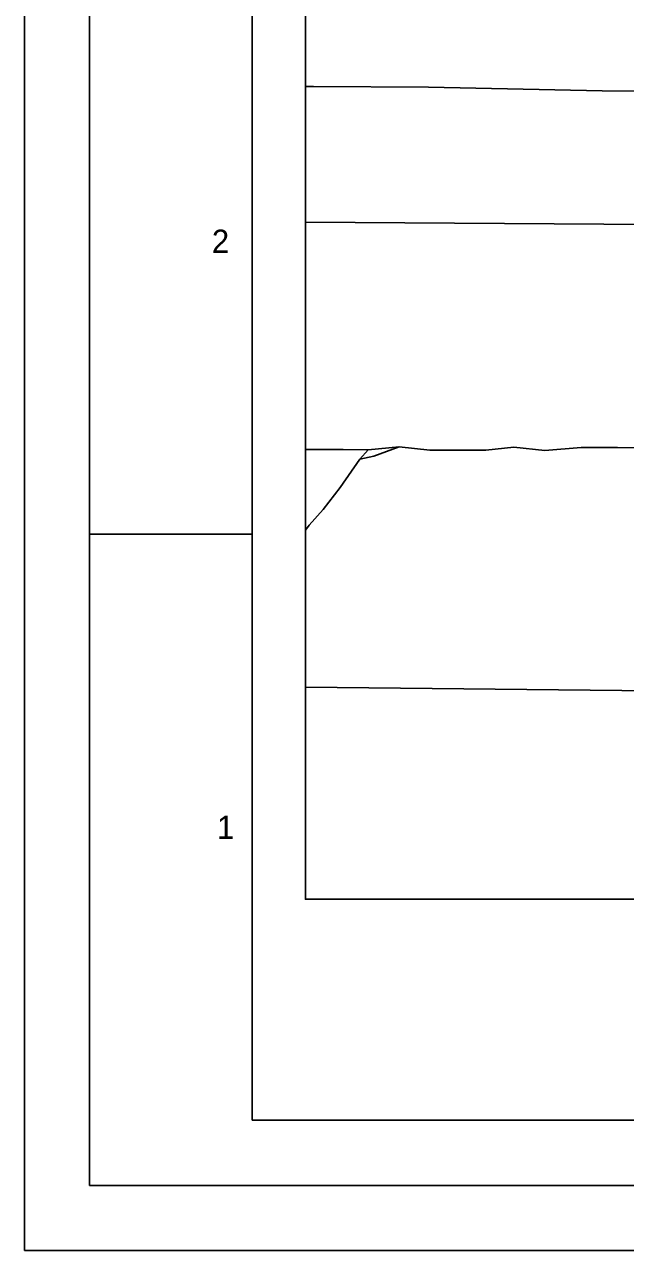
# Model space of a CAD drawing. Extents: x 492225 to 553725, y 1303773 to 1347273.
# Drawn here: x 492225 to 499152, y 1303773 to 1317894 of the extents above; entities that cross this region are included whole.
import ezdxf

# ---------------------------------------------------------------- set-up
doc = ezdxf.new("R2010")
doc.units = 0
for name, color, linetype in [('G-ANNO-TTLB', 7, 'Continuous'), ('Level 1', 7, 'Continuous'), ('Level 13', 7, 'Continuous'), ('Level 22', 7, 'Continuous'), ('Level 52', 7, 'Continuous')]:
    doc.layers.add(name, color=color, linetype=linetype)

msp = doc.modelspace()

# ---------------------------------------------------------------- linework, layer by layer
at = {"layer": 'G-ANNO-TTLB'}
for p, q in [((492975.069, 1346522.564), (492975.069, 1304522.564)), ((494850.069, 1305272.564), (494850.069, 1345772.564)), ((494850.069, 1312022.564), (492975.069, 1312022.564)), ((552225.069, 1305272.564), (494850.069, 1305272.564)), ((492975.069, 1304522.564), (552975.069, 1304522.564))]:
    msp.add_line(p, q, dxfattribs=at)
for points in [[(492225.069, 1303772.564), (553725.069, 1303772.564), (553725.069, 1347272.564), (492225.069, 1347272.564)], [(492225.069, 1303772.564), (553725.069, 1303772.564), (553725.069, 1347272.564), (492225.069, 1347272.564)], [(492225.069, 1347272.564), (553725.069, 1347272.564), (553725.069, 1303772.564), (492225.069, 1303772.564)]]:
    msp.add_lwpolyline(points, close=True, dxfattribs=at)
msp.add_lwpolyline([(492225.069, 1304147.564), (492225.069, 1303772.564), (492600.069, 1303772.564)], dxfattribs=at)
at = {"layer": 'Level 1'}
for p, q in [((499586.966, 1315590.825), (495463.793, 1315618.6072)), ((499556.27, 1310217.447), (495463.793, 1310260.1265))]:
    msp.add_line(p, q, dxfattribs=at)
at = {"layer": 'Level 13'}
for p, q in [((495556.486, 1317179.363), (495463.793, 1317179.7412)), ((496882.035, 1317174.001), (495556.486, 1317179.363)), ((498883.449, 1317129.632), (496882.035, 1317174.001)), ((499561.398, 1317126.942), (498883.449, 1317129.632))]:
    msp.add_line(p, q, dxfattribs=at)
at = {"layer": 'Level 22'}
for p, q in [((496542.439, 1313030.823), (496187.139, 1312995.903)), ((496542.439, 1313030.823), (496251.418, 1312922.932)), ((496897.445, 1312993.037), (496542.439, 1313030.823)), ((497866.191, 1313025.503), (497543.179, 1312990.442)), ((498221.198, 1312987.728), (497866.191, 1313025.503)), ((495509.119, 1312998.652), (495463.793, 1312998.8362)), ((495896.559, 1312997.079), (495509.119, 1312998.652)), ((496089.837, 1312887.229), (495862.5, 1312560.949)), ((496187.139, 1312995.903), (495896.559, 1312997.079)), ((496187.139, 1312995.903), (496089.837, 1312887.229)), ((496251.418, 1312922.932), (496089.837, 1312887.229)), ((497220.313, 1312991.738), (496897.445, 1312993.037)), ((497543.179, 1312990.442), (497220.313, 1312991.738)), ((498641.069, 1313022.41), (498221.198, 1312987.728)), ((499060.795, 1313020.741), (498641.069, 1313022.41)), ((499545.094, 1313018.819), (499060.795, 1313020.741)), ((495862.5, 1312560.949), (495667.744, 1312307.249)), ((495667.744, 1312307.249), (495505.569, 1312126.13)), ((495505.569, 1312126.13), (495463.793, 1312069.1274))]:
    msp.add_line(p, q, dxfattribs=at)
at = {"layer": 'Level 52'}
msp.add_lwpolyline([(518939.5614, 1342691.8404), (495463.7934, 1342691.8404), (495463.7934, 1307817.676), (518939.5614, 1307817.676)], close=True, dxfattribs=at)

# ---------------------------------------------------------------- texts
at = {"layer": 'G-ANNO-TTLB'}
for s, p in [('2', (494385.069, 1315264.064)), ('1', (494443.569, 1308514.064))]:
    msp.add_text(s, height=267.507, dxfattribs=at).set_placement(p)

doc.saveas('drawing.dxf')
